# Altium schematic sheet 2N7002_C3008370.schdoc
size 127 x 101 mm
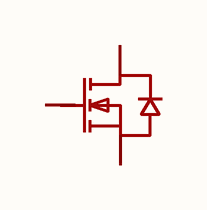
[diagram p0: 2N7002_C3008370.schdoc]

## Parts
Q?  2n7002_c3008370  [SOT-23-3_L2.9-W1.3-P1.90-LS2.4-BR]  (value not drawn)

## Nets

Not connected (* = marked no-connect by the designer): Q? 1(G) 2(S) 3(D)

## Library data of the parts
Q? = 2n7002_c3008370: 数量:1个N沟道;漏源电压(Vdss):60V;连续漏极电流(Id):115mA;导通电阻(RDS(on)):5Ω@10V；7Ω@5V;耗散功率(Pd):225mW;阈值电压(Vgs(th)):2.5V;; Manufacturer: UMW(友台半导体); ManufacturerPart: 2N7002; AddInBom: yes; ModelId: c62791f0466c4ae2a892c056b845b0ca; ModelName: SOT-23-3P_L2.9-W1.3-H1.0-LS2.4-P0.95; ModelTransform: 98.425,114.173,0,180,0,0,0.0005,-0.0005,0; Number: 1个N沟道; Drain to Source Voltage: 60V; Current - Continuous Drain(Id): 115mA; Pd - Power Dissipation: 225mW; Gate Threshold Voltage (Vgs(th)): 2.5V; Input Capacitance(Ciss): 50pF; Reverse Transfer Capacitance (Crss@Vds): 5pF; Type: N沟道; Output Capacitance(Coss): 25pF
